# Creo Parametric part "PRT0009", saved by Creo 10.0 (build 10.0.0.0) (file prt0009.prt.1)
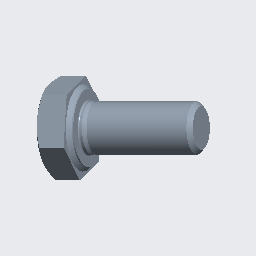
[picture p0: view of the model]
Units: millimeter Newton Second (mmNs); MM, TONNE, SECS

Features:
  1. coordinate system "SCHRAUBEN"
  2. imported feature "Import-ke ID 4"

Surfaces: 14 cone, 11 plane, 6 cylinder, 2 torus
